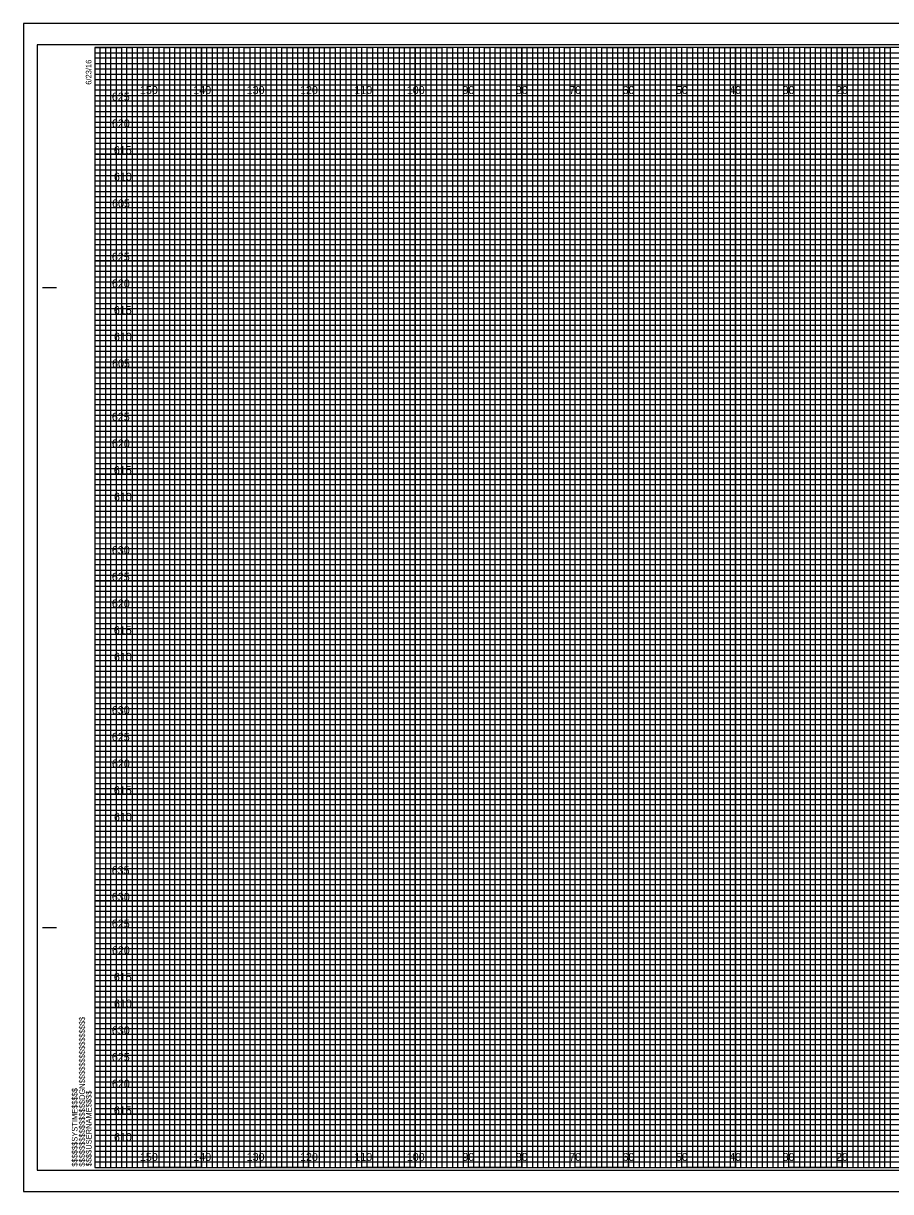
# Model space of a CAD drawing. Extents: x -13 to 323, y 6816 to 7034.
# Drawn here: x -13.4 to 149.1, y 6815.5 to 7034.5 of the extents above; entities that cross this region are included whole.
import ezdxf

# ---------------------------------------------------------------- set-up
doc = ezdxf.new("R2010")
doc.units = 0
for name, color, linetype in [('Exist XS Center Line Elevation Label', 7, 'Continuous'), ('Exist XS Ground Line', 7, 'Continuous'), ('Prop XS Dump Level', 7, 'Continuous'), ('Prop XS Finish Grade', 7, 'Continuous'), ('Prop XS Finish Grade Earthwork', 7, 'Continuous'), ('Prop XS Hydro Elevations', 7, 'Continuous'), ('Prop XS Pvmt Edge Slope', 7, 'Continuous'), ('Prop XS SE Text', 7, 'Continuous'), ('Prop XS Side Slope Text', 7, 'Continuous'), ('Prop XS Subgrade Earthwork', 7, 'Continuous'), ('Scratch_Level_3', 7, 'Continuous')]:
    doc.layers.add(name, color=color, linetype=linetype)

msp = doc.modelspace()

# ---------------------------------------------------------------- linework, layer by layer
at = {"layer": 'Exist XS Center Line Elevation Label'}
for p, q in [((10, 7030), (0, 7030)), ((10, 6820), (10, 7030)), ((30, 7030), (20, 7030)), ((20, 7030), (20, 6820)), ((30, 6820), (30, 7030)), ((50, 7030), (40, 7030)), ((40, 7030), (40, 6820)), ((50, 6820), (50, 7030)), ((70, 7030), (60, 7030)), ((60, 7030), (60, 6820)), ((70, 6820), (70, 7030)), ((90, 7030), (80, 7030)), ((80, 7030), (80, 6820)), ((90, 6820), (90, 7030)), ((110, 7030), (100, 7030)), ((100, 7030), (100, 6820)), ((110, 6820), (110, 7030)), ((130, 7030), (120, 7030)), ((120, 7030), (120, 6820)), ((130, 6820), (130, 7030)), ((150, 7030), (140, 7030)), ((140, 7030), (140, 6820)), ((20, 6820), (10, 6820)), ((40, 6820), (30, 6820)), ((60, 6820), (50, 6820)), ((80, 6820), (70, 6820)), ((100, 6820), (90, 6820)), ((120, 6820), (110, 6820)), ((140, 6820), (130, 6820))]:
    msp.add_line(p, q, dxfattribs=at)
for points in [[(0, 7020), (320, 7020), (320, 7010), (0, 7010)], [(0, 7000), (320, 7000), (320, 6990), (0, 6990)], [(0, 6980), (320, 6980), (320, 6970), (0, 6970)], [(0, 6960), (320, 6960), (320, 6950), (0, 6950)], [(0, 6940), (320, 6940), (320, 6930), (0, 6930)], [(0, 6920), (320, 6920), (320, 6910), (0, 6910)], [(0, 6900), (320, 6900), (320, 6890), (0, 6890)], [(0, 6880), (320, 6880), (320, 6870), (0, 6870)], [(0, 6860), (320, 6860), (320, 6850), (0, 6850)], [(0, 6840), (320, 6840), (320, 6830), (0, 6830)]]:
    msp.add_lwpolyline(points, dxfattribs=at)
at = {"layer": 'Prop XS Dump Level'}
for p, q in [((0, 7029), (260, 7029)), ((260, 7027.98), (0, 7027.98)), ((0, 7027.98), (0, 7027)), ((0, 7027), (260, 7027)), ((260, 7025.89), (0, 7025.89)), ((0, 7025.89), (0, 7024)), ((0, 7024), (320, 7024))]:
    msp.add_line(p, q, dxfattribs=at)
for points in [[(0, 7023), (270, 7023), (320, 7023), (320, 7022), (0, 7022)], [(0, 7021), (320, 7021), (320, 7019), (0, 7019)], [(0, 7018), (320, 7018), (320, 7017), (0, 7016.98)], [(0, 7016), (320, 7016), (320, 7014), (0, 7014)], [(0, 7013), (320, 7013), (320, 7012), (0, 7012)], [(0, 7011), (320, 7011), (320, 7009), (0, 7009)], [(0, 7008), (320, 7008), (320, 7007), (0, 7007)], [(0, 7006), (320, 7006), (320, 7004), (0, 7004)], [(0, 7003), (320, 7003), (320, 7002), (0, 7002)], [(0, 7001), (320, 7001), (320, 6999), (0, 6999)], [(0, 6998), (320, 6998), (320, 6997), (0, 6997)], [(0, 6996), (320, 6996), (320, 6993.95), (320, 6993), (320, 6992), (0, 6992)], [(0, 6994), (320, 6994), (320, 6993), (0, 6993)], [(0, 6991), (320, 6991), (320, 6989), (0, 6989.03)], [(0, 6989.03), (320, 6989), (320, 6988), (0, 6988)], [(0, 6987), (320, 6987), (320, 6986), (0, 6986)], [(0, 6984), (320, 6984), (320, 6983), (0, 6983)], [(0, 6982), (320, 6982), (320, 6981), (0, 6981)], [(-0.07, 6978.89), (320, 6978.89), (320, 6977.88), (-0.07, 6977.88)], [(0, 6977), (320, 6977), (320, 6976), (0, 6976)], [(0, 6974), (320, 6974), (320, 6973), (0, 6973)], [(0, 6972), (320, 6972), (320, 6971), (0, 6971)], [(0, 6969), (320, 6969), (320, 6968), (0, 6968)], [(0, 6967), (320, 6967), (320, 6966), (0, 6966)], [(0, 6964), (320, 6964), (320, 6963), (0, 6963)], [(0, 6962), (320, 6962), (320, 6961), (0, 6961)], [(0, 6959), (320, 6959), (319.99, 6957.98), (0, 6958)], [(0, 6957), (320, 6957), (320, 6956), (0, 6956)], [(0, 6954), (320, 6954), (320, 6953), (0, 6953)], [(0, 6952), (320, 6952), (320, 6951), (0, 6951)], [(0, 6949), (320, 6949), (320, 6948), (0, 6948)], [(0, 6947), (320, 6947), (320, 6946), (0, 6946)], [(0, 6944), (320, 6944), (320, 6943), (0, 6943)], [(0, 6942), (320, 6942), (320, 6941), (0, 6941)], [(0, 6939), (320, 6939), (320, 6938), (0, 6938)], [(0, 6936.99), (320.07, 6936.91), (320, 6936), (0, 6936)], [(0, 6934), (320, 6934), (320, 6933), (0, 6933)], [(0, 6932), (320, 6932), (320, 6931), (0, 6931)], [(0, 6929), (320, 6929), (320, 6928), (0, 6928)], [(0, 6927), (320, 6927), (320, 6926), (0, 6926)], [(0, 6924), (320, 6924), (320, 6923), (0, 6923)], [(0, 6922), (320, 6922), (320, 6921), (0, 6921)], [(0, 6919), (320, 6919), (320, 6918), (0, 6918)], [(0, 6917), (320, 6917), (320, 6916), (0, 6916)], [(0, 6914), (320, 6914), (320, 6913), (0, 6913)], [(0, 6912), (320, 6912), (320, 6911), (0, 6911)], [(0, 6909), (320, 6909), (320, 6908), (0, 6908)], [(0, 6907), (320, 6907), (320, 6906), (0, 6906)], [(0, 6904), (320, 6904), (320, 6903), (0, 6903)], [(0, 6902), (320, 6902), (320, 6901), (0, 6901)], [(0, 6899), (320, 6899), (319.99, 6897.98), (0, 6898)], [(0, 6897), (320, 6897), (320, 6896), (0, 6896)], [(0, 6894), (320, 6894), (320, 6893), (0, 6893)], [(0, 6892), (320, 6892), (320, 6891), (0, 6891)], [(0, 6889), (320, 6889), (320, 6888), (0, 6888)], [(0, 6887), (320, 6887), (320, 6886), (0, 6886)], [(0, 6884), (320, 6884), (320, 6883), (0, 6883)], [(0, 6882), (320, 6882), (320, 6881), (0, 6881)], [(0, 6879), (320, 6879), (320, 6878), (0, 6878)], [(0, 6876.99), (320.07, 6876.91), (320, 6876), (0, 6876)], [(0, 6874), (320, 6874), (320, 6873), (0, 6873)], [(0, 6872), (320, 6872), (320, 6871), (0, 6871)], [(0, 6869), (320, 6869), (320, 6868), (0, 6868)], [(0, 6867), (320, 6867), (320, 6866), (0, 6866)], [(0, 6864), (320, 6864), (320, 6863), (0, 6863)], [(0, 6862), (320, 6862), (320, 6861), (0, 6861)], [(0, 6859), (320, 6859), (320, 6858), (0, 6858)], [(0, 6857), (320, 6857), (320, 6856), (0, 6856)], [(0, 6854), (320, 6854), (320, 6853), (0, 6853)], [(0, 6852), (320, 6852), (320, 6851), (0, 6851)], [(0, 6849), (320, 6849), (320, 6848), (0, 6848)], [(0, 6847), (320, 6847), (320, 6846), (0, 6846)], [(0, 6844), (320, 6844), (320, 6843), (0, 6843)], [(0, 6842), (320, 6842), (320, 6841), (0, 6841)], [(0, 6839), (320, 6839), (320, 6838), (0, 6838)], [(0, 6837), (320, 6837), (320, 6836), (0, 6836)], [(0, 6834), (320, 6834), (320, 6833), (0, 6833)], [(0, 6832), (320, 6832), (320, 6831), (0, 6831)], [(0, 6829), (320, 6829), (320, 6828), (0, 6828)], [(0, 6827), (320, 6827), (320, 6826), (0, 6826)], [(0, 6824), (320, 6824), (320, 6823), (0, 6823)], [(0, 6822), (320, 6822), (320, 6821), (0, 6821)]]:
    msp.add_lwpolyline(points, dxfattribs=at)
at = {"layer": 'Prop XS Finish Grade'}
for p, q in [((323.3, 7034.5), (-13.4, 7034.5)), ((-13.4, 7034.5), (-13.4, 6815.5)), ((-13.4, 6815.5), (323.3, 6815.5))]:
    msp.add_line(p, q, dxfattribs=at)
at = {"layer": 'Prop XS Finish Grade Earthwork'}
msp.add_lwpolyline([(-10.8, 6819.5), (322.4, 6819.5), (322.4, 7030.5), (-10.8, 7030.5)], close=True, dxfattribs=at)
at = {"layer": 'Prop XS Hydro Elevations'}
for points in [[(0, 6820), (1, 6820), (1, 7030), (2, 7030), (2, 6820)], [(2, 6820), (3, 6820), (3, 7030), (4, 7030), (4, 6820)], [(5, 6820), (6, 6820), (6, 7030), (7, 7030), (7, 6820)], [(7, 6820), (8, 6820), (8, 7030), (9, 7030), (9, 6820)], [(10, 6820), (11, 6820), (11, 7030), (12, 7030), (12, 6820)], [(12, 6820), (13, 6820), (13, 7030), (14, 7030), (14, 6820)], [(15, 6820), (16, 6820), (16, 7030), (17, 7030), (17, 6820)], [(17, 6820), (18, 6820), (18, 7030), (19, 7030), (19, 6820)], [(20, 6820), (21, 6820), (21, 7030), (22, 7030), (22, 6820)], [(22, 6820), (23, 6820), (23, 7030), (24, 7030), (24, 6820)], [(25, 6820), (26, 6820), (26, 7030), (27, 7030), (27, 6820)], [(27, 6820), (28, 6820), (28, 7030), (29, 7030), (29, 6820)], [(30, 6820), (31, 6820), (31, 7030), (32, 7030), (32, 6820)], [(32, 6820), (33, 6820), (33, 7030), (34, 7030), (34, 6820)], [(35, 6820), (36, 6820), (36, 7030), (37, 7030), (37, 6820)], [(37, 6820), (38, 6820), (38, 7030), (39, 7030), (39, 6820)], [(40, 6820), (41, 6820), (41, 7030), (42, 7030), (42, 6820)], [(42, 6820), (43, 6820), (43, 7030), (44, 7030), (44, 6820)], [(45, 6820), (46, 6820), (46, 7030), (47, 7030), (47, 6820)], [(47, 6820), (48, 6820), (48, 7030), (49, 7030), (49, 6820)], [(50, 6820), (51, 6820), (51, 7030), (52, 7030), (52, 6820)], [(52, 6820), (53, 6820), (53, 7030), (54, 7030), (54, 6820)], [(55, 6820), (56, 6820), (56, 7030), (57, 7030), (57, 6820)], [(57, 6820), (58, 6820), (58, 7030), (59, 7030), (59, 6820)], [(60, 6820), (61, 6820), (61, 7030), (62, 7030), (62, 6820)], [(62, 6820), (63, 6820), (63, 7030), (64, 7030), (64, 6820)], [(65, 6820), (66, 6820), (66, 7030), (67, 7030), (67, 6820)], [(67, 6820), (68, 6820), (68, 7030), (69, 7030), (69, 6820)], [(70, 6820), (71, 6820), (71, 7030), (72, 7030), (72, 6820)], [(72, 6820), (73, 6820), (73, 7030), (74, 7030), (74, 6820)], [(75, 6820), (76, 6820), (76, 7030), (77, 7030), (77, 6820)], [(77, 6820), (78, 6820), (78, 7030), (79, 7030), (79, 6820)], [(80, 6820), (81, 6820), (81, 7030), (82, 7030), (82, 6820)], [(82, 6820), (83, 6820), (83, 7030), (84, 7030), (84, 6820)], [(85, 6820), (86, 6820), (86, 7030), (87, 7030), (87, 6820)], [(87, 6820), (88, 6820), (88, 7030), (89, 7030), (89, 6820)], [(90, 6820), (91, 6820), (91, 7030), (92, 7030), (92, 6820)], [(92, 6820), (93, 6820), (93, 7030), (94, 7030), (94, 6820)], [(95, 6820), (96, 6820), (96, 7030), (97, 7030), (97, 6820)], [(97, 6820), (98, 6820), (98, 7030), (99, 7030), (99, 6820)], [(100, 6820), (101, 6820), (101, 7030), (102, 7030), (102, 6820)], [(102, 6820), (103, 6820), (103, 7030), (104, 7030), (104, 6820)], [(105, 6820), (106, 6820), (106, 7030), (107, 7030), (107, 6820)], [(107, 6820), (108, 6820), (108, 7030), (109, 7030), (109, 6820)], [(110, 6820), (111, 6820), (111, 7030), (112, 7030), (112, 6820)], [(112, 6820), (113, 6820), (113, 7030), (114, 7030), (114, 6820)], [(115, 6820), (116, 6820), (116, 7030), (117, 7030), (117, 6820)], [(117, 6820), (118, 6820), (118, 7030), (119, 7030), (119, 6820)], [(120, 6820), (121, 6820), (121, 7030), (122, 7030), (122, 6820)], [(122, 6820), (123, 6820), (123, 7030), (124, 7030), (124, 6820)], [(125, 6820), (126, 6820), (126, 7030), (127, 7030), (127, 6820)], [(127, 6820), (128, 6820), (128, 7030), (129, 7030), (129, 6820)], [(130, 6820), (131, 6820), (131, 7030), (132, 7030), (132, 6820)], [(132, 6820), (133, 6820), (133, 7030), (134, 7030), (134, 6820)], [(135, 6820), (136, 6820), (136, 7030), (137, 7030), (137, 6820)], [(137, 6820), (138, 6820), (138, 7030), (139, 7030), (139, 6820)], [(140, 6820), (141, 6820), (141, 7030), (142, 7030), (142, 6820)], [(142, 6820), (143, 6820), (143, 7030), (144, 7030), (144, 6820)], [(145, 6820), (146, 6820), (146, 7030), (147, 7030), (147, 6820)], [(147, 6820), (148, 6820), (148, 7030), (149, 7030), (149, 6820)]]:
    msp.add_lwpolyline(points, dxfattribs=at)
at = {"layer": 'Prop XS Pvmt Edge Slope'}
for p, q in [((10, 6820), (10, 7030)), ((20, 6820), (20, 7030)), ((30, 6820), (30, 7030)), ((40, 6820), (40, 7030)), ((50, 6820), (50, 7030)), ((60, 6820), (60, 7030)), ((70, 6820), (70, 7030)), ((80, 6820), (80, 7030)), ((90, 6820), (90, 7030)), ((100, 6820), (100, 7030)), ((110, 6820), (110, 7030)), ((120, 6820), (120, 7030)), ((130, 6820), (130, 7030)), ((140, 6820), (140, 7030)), ((0, 7020), (320, 7020)), ((0, 7010), (320, 7010)), ((0, 7000), (320, 7000)), ((0, 6990), (320, 6990)), ((0, 6980), (320, 6980)), ((0, 6970), (320, 6970)), ((0, 6960), (320, 6960)), ((0, 6950), (320, 6950)), ((0, 6940), (320, 6940)), ((0, 6930), (320, 6930)), ((0, 6920), (320, 6920)), ((0, 6910), (320, 6910)), ((0, 6900), (320, 6900)), ((0, 6890), (320, 6890)), ((0, 6880), (320, 6880)), ((0, 6870), (320, 6870)), ((0, 6860), (320, 6860)), ((0, 6850), (320, 6850)), ((0, 6840), (320, 6840)), ((0, 6830), (320, 6830))]:
    msp.add_line(p, q, dxfattribs=at)
at = {"layer": 'Prop XS SE Text'}
for p, q in [((-9.8, 6985), (-7.3, 6985)), ((-9.7, 6985), (-7.2, 6985)), ((-9.8, 6865), (-7.3, 6865)), ((-9.7, 6865), (-7.2, 6865)), ((0, 6820), (0, 6820)), ((0, 6820), (0, 6820)), ((0, 6820), (0, 6820)), ((0, 6820), (0, 6820)), ((0, 6820), (0, 6820)), ((0, 6820), (0, 6820)), ((0, 6820), (0, 6820))]:
    msp.add_line(p, q, dxfattribs=at)
msp.add_lwpolyline([(320, 7030), (0, 7030), (0, 6820), (320, 6820)], close=True, dxfattribs=at)
at = {"layer": 'Prop XS Side Slope Text'}
msp.add_lwpolyline([(-13.4, 6815.5), (323.3, 6815.5), (323.3, 7034.5), (-13.4, 7034.5)], close=True, dxfattribs=at)
at = {"layer": 'Scratch_Level_3'}
for points in [[(0, 7030), (5, 7030), (5, 6820), (15, 6820), (15, 7030), (25, 7030), (25, 6820), (35, 6820), (35, 7030), (45, 7030), (45, 6820), (55, 6820), (55, 7030), (65, 7030), (65, 6820), (75, 6820), (75, 7030), (85, 7030), (85, 6820), (95, 6820), (95, 7030), (105, 7030), (105, 6820), (115, 6820), (115, 7030), (125, 7030), (125, 6820), (135, 6820), (135, 7030), (145, 7030), (145, 6820), (155, 6820)], [(0, 7025), (275, 7025)], [(0, 7005), (320, 7005), (320, 7015), (0, 7015)], [(0, 6985), (320, 6985), (320, 6995), (0, 6995)], [(0, 6965), (320, 6965), (320, 6975), (0, 6975)], [(0, 6945), (320, 6945), (320, 6955), (0, 6955)], [(0, 6925), (320, 6925), (320, 6935), (0, 6935)], [(0, 6905), (320, 6905), (320, 6915), (0, 6915)], [(0, 6885), (320, 6885), (320, 6895), (0, 6895)], [(0, 6865), (320, 6865), (320, 6875), (0, 6875)], [(0, 6845), (320, 6845), (320, 6855), (0, 6855)], [(0, 6825), (320, 6825), (320, 6835), (0, 6835)]]:
    msp.add_lwpolyline(points, dxfattribs=at)

# ---------------------------------------------------------------- texts
at = {"layer": 'Exist XS Ground Line'}
for s, p in [('150', (8.44, 7021.25)), ('140', (18.44, 7021.25)), ('130', (28.44, 7021.25)), ('120', (38.44, 7021.25)), ('110', (48.62, 7021.25)), ('100', (58.44, 7021.25)), ('90', (68.86, 7021.25)), ('80', (78.86, 7021.25)), ('70', (88.86, 7021.25)), ('60', (98.86, 7021.25)), ('50', (108.86, 7021.25)), ('40', (118.86, 7021.25)), ('30', (128.86, 7021.25)), ('20', (138.86, 7021.25)), ('150', (8.44, 6821.25)), ('140', (18.44, 6821.25)), ('130', (28.44, 6821.25)), ('120', (38.44, 6821.25)), ('110', (48.62, 6821.25)), ('100', (58.44, 6821.25)), ('90', (68.86, 6821.25)), ('80', (78.86, 6821.25)), ('70', (88.86, 6821.25)), ('60', (98.86, 6821.25)), ('50', (108.86, 6821.25)), ('40', (118.86, 6821.25)), ('30', (128.86, 6821.25)), ('20', (138.86, 6821.25))]:
    msp.add_text(s, height=1.5, dxfattribs=at).set_placement(p)
at = {"layer": 'Prop XS SE Text'}
for s, p in [('6/23/16', (-0.65, 7023)), ('$$$$$$$$$$$$$$$$DGN$$$$$$$$$$$$$$$$', (-1.88, 6820.18)), ('$$$$$$SYSTIME$$$$$', (-3.26, 6820.18)), ('$$$$USERNAME$$$$', (-0.62, 6820.23))]:
    msp.add_text(s, height=1.05, rotation=90, dxfattribs=at).set_placement(p)
at = {"layer": 'Prop XS Subgrade Earthwork'}
for s, p in [('625', (3.18, 7020)), ('620', (3.19, 7015)), ('615', (3.55, 7010)), ('610', (3.57, 7005)), ('605', (3.22, 7000)), ('625', (3.18, 6990)), ('620', (3.19, 6985)), ('615', (3.55, 6980)), ('610', (3.57, 6975)), ('605', (3.22, 6970)), ('625', (3.18, 6960)), ('620', (3.19, 6955)), ('615', (3.55, 6950)), ('610', (3.57, 6945)), ('630', (3.18, 6935)), ('625', (3.18, 6930)), ('620', (3.19, 6925)), ('615', (3.55, 6920)), ('610', (3.57, 6915)), ('630', (3.18, 6905)), ('625', (3.18, 6900)), ('620', (3.19, 6895)), ('615', (3.55, 6890)), ('610', (3.57, 6885)), ('635', (3.16, 6875)), ('630', (3.18, 6870)), ('625', (3.18, 6865)), ('620', (3.19, 6860)), ('615', (3.55, 6855)), ('610', (3.57, 6850)), ('630', (3.18, 6844.98)), ('625', (3.18, 6839.98)), ('620', (3.19, 6834.98)), ('615', (3.55, 6829.98)), ('610', (3.57, 6824.98))]:
    msp.add_text(s, height=1.5, dxfattribs=at).set_placement(p)

doc.saveas('drawing.dxf')
